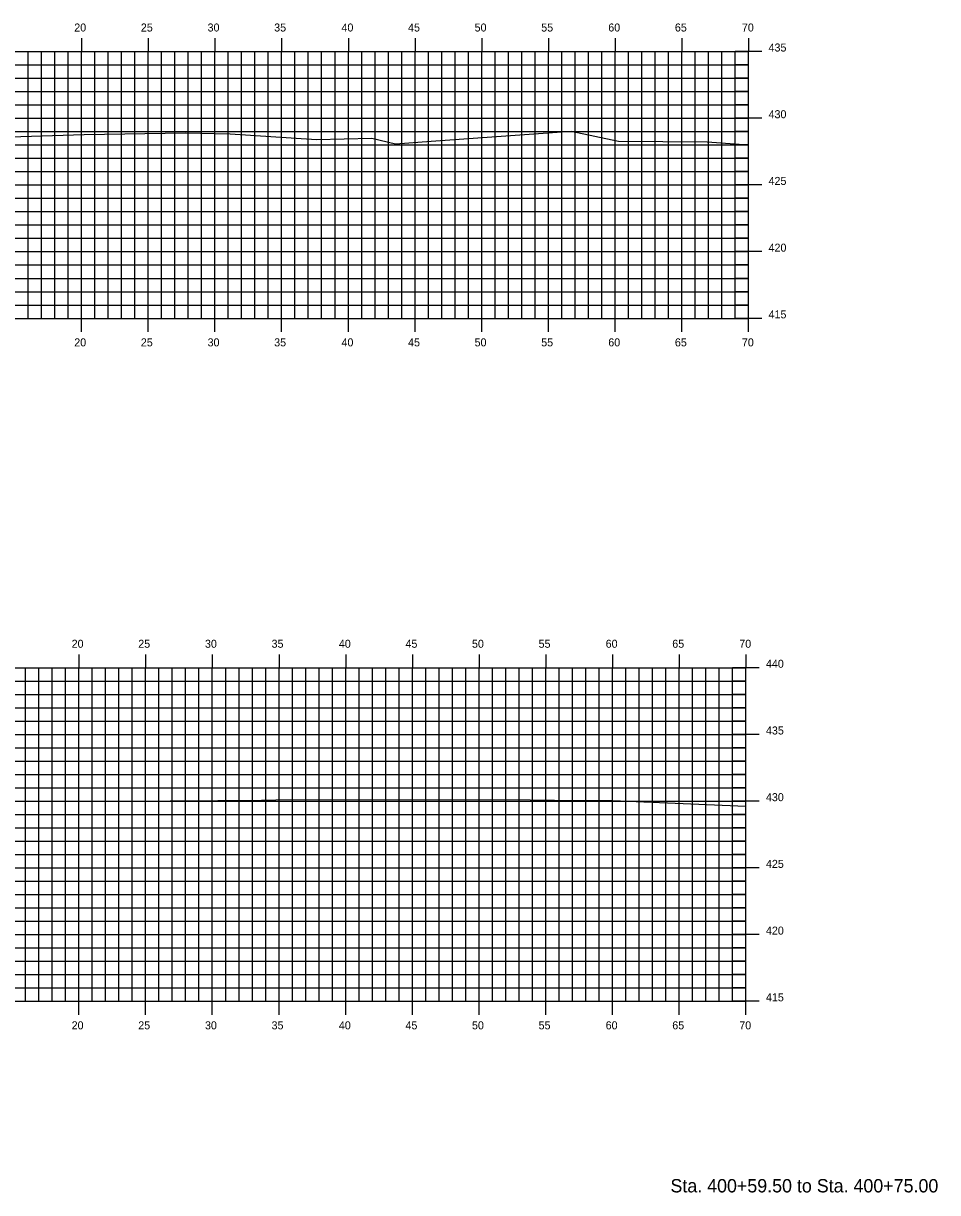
# Model space of a CAD drawing. Extents: x -161 to 764, y 111 to 210.
# Drawn here: x 426.2 to 494.8, y 110.7 to 198.4 of the extents above; entities that cross this region are included whole.
import ezdxf

# ---------------------------------------------------------------- set-up
doc = ezdxf.new("R2010")
doc.units = 0
for name, color, linetype in [('H_V ANNOTATION', 7, 'Continuous'), ('MAJOR', 7, 'Continuous'), ('MINOR', 7, 'Continuous'), ('S_Roadway_Centerline', 7, 'Continuous')]:
    doc.layers.add(name, color=color, linetype=linetype)

msp = doc.modelspace()

# ---------------------------------------------------------------- linework, layer by layer
at = {"layer": 'MAJOR'}
for p, q in [((430.591, 197.249), (430.591, 196.247)), ((435.591, 197.249), (435.591, 196.247)), ((440.591, 197.249), (440.591, 196.247)), ((445.591, 197.249), (445.591, 196.247)), ((450.591, 197.249), (450.591, 196.247)), ((455.591, 197.249), (455.591, 196.247)), ((460.591, 197.249), (460.591, 196.247)), ((465.591, 197.249), (465.591, 196.247)), ((470.591, 197.249), (470.591, 196.247)), ((475.591, 197.249), (475.591, 196.247)), ((480.591, 197.249), (480.591, 196.247)), ((340.591, 196.247), (480.591, 196.247)), ((340.591, 196.247), (480.591, 196.247)), ((430.591, 176.247), (430.591, 196.247)), ((435.591, 176.247), (435.591, 196.247)), ((440.591, 176.247), (440.591, 196.247)), ((445.591, 176.247), (445.591, 196.247)), ((450.591, 176.247), (450.591, 196.247)), ((455.591, 176.247), (455.591, 196.247)), ((460.591, 176.247), (460.591, 196.247)), ((465.591, 176.247), (465.591, 196.247)), ((470.591, 176.247), (470.591, 196.247)), ((475.591, 176.247), (475.591, 196.247)), ((481.593, 196.247), (479.589, 196.247)), ((480.591, 176.247), (480.591, 196.247)), ((480.591, 176.247), (480.591, 196.247)), ((340.591, 191.247), (480.591, 191.247)), ((481.593, 191.247), (479.589, 191.247)), ((340.591, 186.247), (480.591, 186.247)), ((481.593, 186.247), (479.589, 186.247)), ((340.591, 181.247), (480.591, 181.247)), ((481.593, 181.247), (479.589, 181.247)), ((340.591, 176.247), (480.591, 176.247)), ((340.591, 176.247), (480.591, 176.247)), ((430.591, 175.245), (430.591, 176.247)), ((435.591, 175.245), (435.591, 176.247)), ((440.591, 175.245), (440.591, 176.247)), ((445.591, 175.245), (445.591, 176.247)), ((450.591, 175.245), (450.591, 176.247)), ((455.591, 175.245), (455.591, 176.247)), ((460.591, 175.245), (460.591, 176.247)), ((465.591, 175.245), (465.591, 176.247)), ((470.591, 175.245), (470.591, 176.247)), ((475.591, 175.245), (475.591, 176.247)), ((481.593, 176.247), (479.589, 176.247)), ((480.591, 175.245), (480.591, 176.247)), ((430.395, 151.06), (430.395, 150.058)), ((435.395, 151.06), (435.395, 150.058)), ((440.395, 151.06), (440.395, 150.058)), ((445.395, 151.06), (445.395, 150.058)), ((450.395, 151.06), (450.395, 150.058)), ((455.395, 151.06), (455.395, 150.058)), ((460.395, 151.06), (460.395, 150.058)), ((465.395, 151.06), (465.395, 150.058)), ((470.395, 151.06), (470.395, 150.058)), ((475.395, 151.06), (475.395, 150.058)), ((480.395, 151.06), (480.395, 150.058)), ((340.395, 150.058), (480.395, 150.058)), ((340.395, 150.058), (480.395, 150.058)), ((430.395, 125.058), (430.395, 150.058)), ((435.395, 125.058), (435.395, 150.058)), ((440.395, 125.058), (440.395, 150.058)), ((445.395, 125.058), (445.395, 150.058)), ((450.395, 125.058), (450.395, 150.058)), ((455.395, 125.058), (455.395, 150.058)), ((460.395, 125.058), (460.395, 150.058)), ((465.395, 125.058), (465.395, 150.058)), ((470.395, 125.058), (470.395, 150.058)), ((475.395, 125.058), (475.395, 150.058)), ((481.397, 150.058), (479.393, 150.058)), ((480.395, 125.058), (480.395, 150.058)), ((480.395, 125.058), (480.395, 150.058)), ((340.395, 145.058), (480.395, 145.058)), ((481.397, 145.058), (479.393, 145.058)), ((340.395, 140.058), (480.395, 140.058)), ((481.397, 140.058), (479.393, 140.058)), ((340.395, 135.058), (480.395, 135.058)), ((481.397, 135.058), (479.393, 135.058)), ((340.395, 130.058), (480.395, 130.058)), ((481.397, 130.058), (479.393, 130.058)), ((340.395, 125.058), (480.395, 125.058)), ((340.395, 125.058), (480.395, 125.058)), ((430.395, 124.056), (430.395, 125.058)), ((435.395, 124.056), (435.395, 125.058)), ((440.395, 124.056), (440.395, 125.058)), ((445.395, 124.056), (445.395, 125.058)), ((450.395, 124.056), (450.395, 125.058)), ((455.395, 124.056), (455.395, 125.058)), ((460.395, 124.056), (460.395, 125.058)), ((465.395, 124.056), (465.395, 125.058)), ((470.395, 124.056), (470.395, 125.058)), ((475.395, 124.056), (475.395, 125.058)), ((481.397, 125.058), (479.393, 125.058)), ((480.395, 124.056), (480.395, 125.058))]:
    msp.add_line(p, q, dxfattribs=at)
at = {"layer": 'MINOR'}
for p, q in [((426.591, 176.247), (426.591, 196.247)), ((427.591, 176.247), (427.591, 196.247)), ((428.591, 176.247), (428.591, 196.247)), ((429.591, 176.247), (429.591, 196.247)), ((431.591, 176.247), (431.591, 196.247)), ((432.591, 176.247), (432.591, 196.247)), ((433.591, 176.247), (433.591, 196.247)), ((434.591, 176.247), (434.591, 196.247)), ((436.591, 176.247), (436.591, 196.247)), ((437.591, 176.247), (437.591, 196.247)), ((438.591, 176.247), (438.591, 196.247)), ((439.591, 176.247), (439.591, 196.247)), ((441.591, 176.247), (441.591, 196.247)), ((442.591, 176.247), (442.591, 196.247)), ((443.591, 176.247), (443.591, 196.247)), ((444.591, 176.247), (444.591, 196.247)), ((446.591, 176.247), (446.591, 196.247)), ((447.591, 176.247), (447.591, 196.247)), ((448.591, 176.247), (448.591, 196.247)), ((449.591, 176.247), (449.591, 196.247)), ((451.591, 176.247), (451.591, 196.247)), ((452.591, 176.247), (452.591, 196.247)), ((453.591, 176.247), (453.591, 196.247)), ((454.591, 176.247), (454.591, 196.247)), ((456.591, 176.247), (456.591, 196.247)), ((457.591, 176.247), (457.591, 196.247)), ((458.591, 176.247), (458.591, 196.247)), ((459.591, 176.247), (459.591, 196.247)), ((461.591, 176.247), (461.591, 196.247)), ((462.591, 176.247), (462.591, 196.247)), ((463.591, 176.247), (463.591, 196.247)), ((464.591, 176.247), (464.591, 196.247)), ((466.591, 176.247), (466.591, 196.247)), ((467.591, 176.247), (467.591, 196.247)), ((468.591, 176.247), (468.591, 196.247)), ((469.591, 176.247), (469.591, 196.247)), ((471.591, 176.247), (471.591, 196.247)), ((472.591, 176.247), (472.591, 196.247)), ((473.591, 176.247), (473.591, 196.247)), ((474.591, 176.247), (474.591, 196.247)), ((476.591, 176.247), (476.591, 196.247)), ((477.591, 176.247), (477.591, 196.247)), ((478.591, 176.247), (478.591, 196.247)), ((479.591, 176.247), (479.591, 196.247)), ((340.591, 195.247), (480.591, 195.247)), ((480.591, 195.247), (479.589, 195.247)), ((340.591, 194.247), (480.591, 194.247)), ((480.591, 194.247), (479.589, 194.247)), ((340.591, 193.247), (480.591, 193.247)), ((480.591, 193.247), (479.589, 193.247)), ((340.591, 192.247), (480.591, 192.247)), ((480.591, 192.247), (479.589, 192.247)), ((340.591, 190.247), (480.591, 190.247)), ((480.591, 190.247), (479.589, 190.247)), ((340.591, 189.247), (480.591, 189.247)), ((480.591, 189.247), (479.589, 189.247)), ((340.591, 188.247), (480.591, 188.247)), ((480.591, 188.247), (479.589, 188.247)), ((340.591, 187.247), (480.591, 187.247)), ((480.591, 187.247), (479.589, 187.247)), ((340.591, 185.247), (480.591, 185.247)), ((480.591, 185.247), (479.589, 185.247)), ((340.591, 184.247), (480.591, 184.247)), ((480.591, 184.247), (479.589, 184.247)), ((340.591, 183.247), (480.591, 183.247)), ((480.591, 183.247), (479.589, 183.247)), ((340.591, 182.247), (480.591, 182.247)), ((480.591, 182.247), (479.589, 182.247)), ((340.591, 180.247), (480.591, 180.247)), ((480.591, 180.247), (479.589, 180.247)), ((340.591, 179.247), (480.591, 179.247)), ((480.591, 179.247), (479.589, 179.247)), ((340.591, 178.247), (480.591, 178.247)), ((480.591, 178.247), (479.589, 178.247)), ((340.591, 177.247), (480.591, 177.247)), ((480.591, 177.247), (479.589, 177.247)), ((426.395, 125.058), (426.395, 150.058)), ((427.395, 125.058), (427.395, 150.058)), ((428.395, 125.058), (428.395, 150.058)), ((429.395, 125.058), (429.395, 150.058)), ((431.395, 125.058), (431.395, 150.058)), ((432.395, 125.058), (432.395, 150.058)), ((433.395, 125.058), (433.395, 150.058)), ((434.395, 125.058), (434.395, 150.058)), ((436.395, 125.058), (436.395, 150.058)), ((437.395, 125.058), (437.395, 150.058)), ((438.395, 125.058), (438.395, 150.058)), ((439.395, 125.058), (439.395, 150.058)), ((441.395, 125.058), (441.395, 150.058)), ((442.395, 125.058), (442.395, 150.058)), ((443.395, 125.058), (443.395, 150.058)), ((444.395, 125.058), (444.395, 150.058)), ((446.395, 125.058), (446.395, 150.058)), ((447.395, 125.058), (447.395, 150.058)), ((448.395, 125.058), (448.395, 150.058)), ((449.395, 125.058), (449.395, 150.058)), ((451.395, 125.058), (451.395, 150.058)), ((452.395, 125.058), (452.395, 150.058)), ((453.395, 125.058), (453.395, 150.058)), ((454.395, 125.058), (454.395, 150.058)), ((456.395, 125.058), (456.395, 150.058)), ((457.395, 125.058), (457.395, 150.058)), ((458.395, 125.058), (458.395, 150.058)), ((459.395, 125.058), (459.395, 150.058)), ((461.395, 125.058), (461.395, 150.058)), ((462.395, 125.058), (462.395, 150.058)), ((463.395, 125.058), (463.395, 150.058)), ((464.395, 125.058), (464.395, 150.058)), ((466.395, 125.058), (466.395, 150.058)), ((467.395, 125.058), (467.395, 150.058)), ((468.395, 125.058), (468.395, 150.058)), ((469.395, 125.058), (469.395, 150.058)), ((471.395, 125.058), (471.395, 150.058)), ((472.395, 125.058), (472.395, 150.058)), ((473.395, 125.058), (473.395, 150.058)), ((474.395, 125.058), (474.395, 150.058)), ((476.395, 125.058), (476.395, 150.058)), ((477.395, 125.058), (477.395, 150.058)), ((478.395, 125.058), (478.395, 150.058)), ((479.395, 125.058), (479.395, 150.058)), ((340.395, 149.058), (480.395, 149.058)), ((480.395, 149.058), (479.393, 149.058)), ((340.395, 148.058), (480.395, 148.058)), ((480.395, 148.058), (479.393, 148.058)), ((340.395, 147.058), (480.395, 147.058)), ((480.395, 147.058), (479.393, 147.058)), ((340.395, 146.058), (480.395, 146.058)), ((480.395, 146.058), (479.393, 146.058)), ((340.395, 144.058), (480.395, 144.058)), ((480.395, 144.058), (479.393, 144.058)), ((340.395, 143.058), (480.395, 143.058)), ((480.395, 143.058), (479.393, 143.058)), ((340.395, 142.058), (480.395, 142.058)), ((480.395, 142.058), (479.393, 142.058)), ((340.395, 141.058), (480.395, 141.058)), ((480.395, 141.058), (479.393, 141.058)), ((340.395, 139.058), (480.395, 139.058)), ((480.395, 139.058), (479.393, 139.058)), ((340.395, 138.058), (480.395, 138.058)), ((480.395, 138.058), (479.393, 138.058)), ((340.395, 137.058), (480.395, 137.058)), ((480.395, 137.058), (479.393, 137.058)), ((340.395, 136.058), (480.395, 136.058)), ((480.395, 136.058), (479.393, 136.058)), ((340.395, 134.058), (480.395, 134.058)), ((480.395, 134.058), (479.393, 134.058)), ((340.395, 133.058), (480.395, 133.058)), ((480.395, 133.058), (479.393, 133.058)), ((340.395, 132.058), (480.395, 132.058)), ((480.395, 132.058), (479.393, 132.058)), ((340.395, 131.058), (480.395, 131.058)), ((480.395, 131.058), (479.393, 131.058)), ((340.395, 129.058), (480.395, 129.058)), ((480.395, 129.058), (479.393, 129.058)), ((340.395, 128.058), (480.395, 128.058)), ((480.395, 128.058), (479.393, 128.058)), ((340.395, 127.058), (480.395, 127.058)), ((480.395, 127.058), (479.393, 127.058)), ((340.395, 126.058), (480.395, 126.058)), ((480.395, 126.058), (479.393, 126.058))]:
    msp.add_line(p, q, dxfattribs=at)
at = {"layer": 'S_Roadway_Centerline'}
for points in [[(422.879, 189.785), (430.793, 190.018), (438.383, 190.15), (441.734, 190.083), (448.214, 189.66), (452.344, 189.748), (454.13, 189.331), (456.802, 189.523), (467.306, 190.287), (470.841, 189.538), (477.49, 189.476), (480.591, 189.252)], [(422.294, 140.074), (433.65, 140.066), (440.81, 140.115), (442.975, 140.109), (445.167, 140.159), (462.416, 140.172), (467.832, 140.11), (470.39, 140.119), (480.395, 139.69)]]:
    msp.add_lwpolyline(points, dxfattribs=at)

# ---------------------------------------------------------------- texts
at = {"layer": 'H_V ANNOTATION'}
for s, height, p in [('20', 0.6, (430.045, 197.747)), ('25', 0.6, (435.037, 197.747)), ('30', 0.6, (440.04, 197.747)), ('35', 0.6, (445.032, 197.747)), ('40', 0.6, (450.077, 197.747)), ('45', 0.6, (455.069, 197.747)), ('50', 0.6, (460.056, 197.747)), ('55', 0.6, (465.048, 197.747)), ('60', 0.6, (470.077, 197.747)), ('65', 0.6, (475.069, 197.747)), ('70', 0.6, (480.093, 197.747)), ('435', 0.6, (482.091, 196.247)), ('430', 0.6, (482.091, 191.247)), ('425', 0.6, (482.091, 186.247)), ('420', 0.6, (482.091, 181.247)), ('415', 0.6, (482.091, 176.247)), ('20', 0.6, (430.045, 174.147)), ('25', 0.6, (435.037, 174.147)), ('30', 0.6, (440.04, 174.147)), ('35', 0.6, (445.032, 174.147)), ('40', 0.6, (450.077, 174.147)), ('45', 0.6, (455.069, 174.147)), ('50', 0.6, (460.056, 174.147)), ('55', 0.6, (465.048, 174.147)), ('60', 0.6, (470.077, 174.147)), ('65', 0.6, (475.069, 174.147)), ('70', 0.6, (480.093, 174.147)), ('20', 0.6, (429.849, 151.558)), ('25', 0.6, (434.841, 151.558)), ('30', 0.6, (439.844, 151.558)), ('35', 0.6, (444.836, 151.558)), ('40', 0.6, (449.881, 151.558)), ('45', 0.6, (454.873, 151.558)), ('50', 0.6, (459.86, 151.558)), ('55', 0.6, (464.852, 151.558)), ('60', 0.6, (469.881, 151.558)), ('65', 0.6, (474.873, 151.558)), ('70', 0.6, (479.897, 151.558)), ('440', 0.6, (481.895, 150.058)), ('435', 0.6, (481.895, 145.058)), ('430', 0.6, (481.895, 140.058)), ('425', 0.6, (481.895, 135.058)), ('420', 0.6, (481.895, 130.058)), ('415', 0.6, (481.895, 125.058)), ('20', 0.6, (429.849, 122.958)), ('25', 0.6, (434.841, 122.958)), ('30', 0.6, (439.844, 122.958)), ('35', 0.6, (444.836, 122.958)), ('40', 0.6, (449.881, 122.958)), ('45', 0.6, (454.873, 122.958)), ('50', 0.6, (459.86, 122.958)), ('55', 0.6, (464.852, 122.958)), ('60', 0.6, (469.881, 122.958)), ('65', 0.6, (474.873, 122.958)), ('70', 0.6, (479.897, 122.958)), ('Sta. 400+59.50 to Sta. 400+75.00', 1.0002, (474.737, 110.734))]:
    msp.add_text(s, height=height, rotation=360, dxfattribs=at).set_placement(p)

doc.saveas('drawing.dxf')
